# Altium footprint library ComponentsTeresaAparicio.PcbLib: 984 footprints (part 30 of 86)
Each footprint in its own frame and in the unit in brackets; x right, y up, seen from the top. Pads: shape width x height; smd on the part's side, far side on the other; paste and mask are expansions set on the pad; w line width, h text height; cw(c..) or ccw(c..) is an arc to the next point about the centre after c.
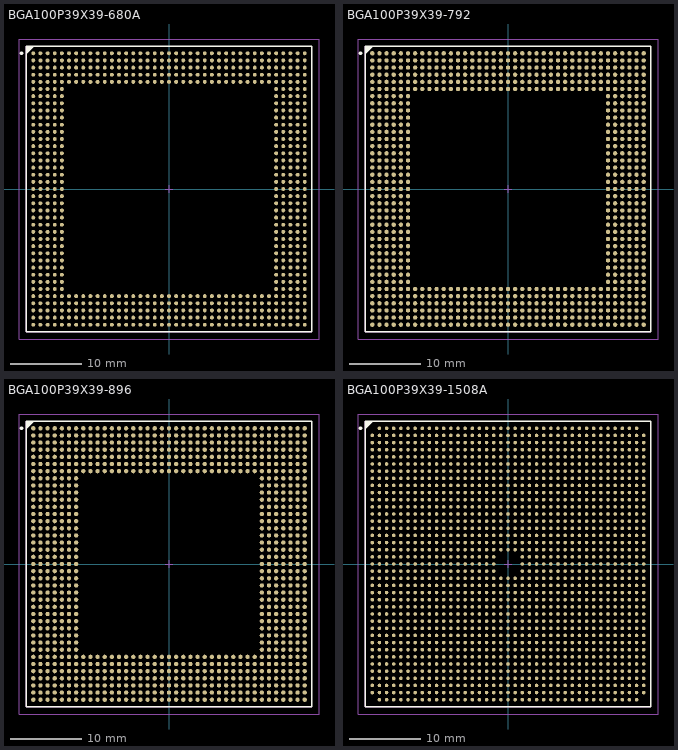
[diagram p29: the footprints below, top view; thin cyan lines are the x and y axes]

## BGA100P39X39-680A [mm] "BGA, 680-Leads, Body 40x40mm, Pitch 1mm"
height 1.7
pads (680):
  round 0.55 smd: A1(-19,19) A2(-18,19) A3(-17,19) A4(-16,19) A5(-15,19) A6(-14,19) A7(-13,19) A8(-12,19) A9(-11,19) A10(-10,19) A11(-9,19) A12(-8,19) A13(-7,19) A14(-6,19) A15(-5,19) A16(-4,19) A17(-3,19) A18(-2,19) A19(-1,19) A20(0,19) A21(1,19) A22(2,19) A23(3,19) A24(4,19) A25(5,19) A26(6,19) A27(7,19) A28(8,19) A29(9,19) A30(10,19) A31(11,19) A32(12,19) A33(13,19) A34(14,19) A35(15,19) A36(16,19) A37(17,19) A38(18,19) A39(19,19) AA1(-19,-1) AA2(-18,-1) AA3(-17,-1) AA4(-16,-1) AA5(-15,-1) AA35(15,-1) AA36(16,-1) AA37(17,-1) AA38(18,-1) AA39(19,-1) AB1(-19,-2) AB2(-18,-2) AB3(-17,-2) AB4(-16,-2) AB5(-15,-2) AB35(15,-2) AB36(16,-2) AB37(17,-2) AB38(18,-2) AB39(19,-2) AC1(-19,-3) AC2(-18,-3) AC3(-17,-3) AC4(-16,-3) AC5(-15,-3) AC35(15,-3) AC36(16,-3) AC37(17,-3) AC38(18,-3) AC39(19,-3) AD1(-19,-4) AD2(-18,-4) AD3(-17,-4) AD4(-16,-4) AD5(-15,-4) AD35(15,-4) AD36(16,-4) AD37(17,-4) AD38(18,-4) AD39(19,-4) AE1(-19,-5) AE2(-18,-5) AE3(-17,-5) AE4(-16,-5) AE5(-15,-5) AE35(15,-5) AE36(16,-5) AE37(17,-5) AE38(18,-5) AE39(19,-5) AF1(-19,-6) AF2(-18,-6) AF3(-17,-6) AF4(-16,-6) AF5(-15,-6) AF35(15,-6) AF36(16,-6) AF37(17,-6) AF38(18,-6) AF39(19,-6) AG1(-19,-7) AG2(-18,-7) AG3(-17,-7) AG4(-16,-7) AG5(-15,-7) AG35(15,-7) AG36(16,-7) AG37(17,-7) AG38(18,-7) AG39(19,-7) AH1(-19,-8) AH2(-18,-8) AH3(-17,-8) AH4(-16,-8) AH5(-15,-8) AH35(15,-8) AH36(16,-8) AH37(17,-8) AH38(18,-8) AH39(19,-8) AJ1(-19,-9) AJ2(-18,-9) AJ3(-17,-9) AJ4(-16,-9) AJ5(-15,-9) AJ35(15,-9) AJ36(16,-9) AJ37(17,-9) AJ38(18,-9) AJ39(19,-9) AK1(-19,-10) AK2(-18,-10) AK3(-17,-10) AK4(-16,-10) AK5(-15,-10) AK35(15,-10) AK36(16,-10) AK37(17,-10) AK38(18,-10) AK39(19,-10) AL1(-19,-11) AL2(-18,-11) AL3(-17,-11) AL4(-16,-11) AL5(-15,-11) AL35(15,-11) AL36(16,-11) AL37(17,-11) AL38(18,-11) AL39(19,-11) AM1(-19,-12) AM2(-18,-12) AM3(-17,-12) AM4(-16,-12) AM5(-15,-12) AM35(15,-12) AM36(16,-12) AM37(17,-12) AM38(18,-12) AM39(19,-12) AN1(-19,-13) AN2(-18,-13) AN3(-17,-13) AN4(-16,-13) AN5(-15,-13) AN35(15,-13) AN36(16,-13) AN37(17,-13) AN38(18,-13) AN39(19,-13) AP1(-19,-14) AP2(-18,-14) AP3(-17,-14) AP4(-16,-14) AP5(-15,-14) AP35(15,-14) AP36(16,-14) AP37(17,-14) AP38(18,-14) AP39(19,-14) AR1(-19,-15) AR2(-18,-15) AR3(-17,-15) AR4(-16,-15) AR5(-15,-15) AR6(-14,-15) AR7(-13,-15) AR8(-12,-15) AR9(-11,-15) AR10(-10,-15) AR11(-9,-15) AR12(-8,-15) AR13(-7,-15) AR14(-6,-15) AR15(-5,-15) AR16(-4,-15) AR17(-3,-15) AR18(-2,-15) AR19(-1,-15) AR20(0,-15) AR21(1,-15) AR22(2,-15) AR23(3,-15) AR24(4,-15) AR25(5,-15) AR26(6,-15) AR27(7,-15) AR28(8,-15) AR29(9,-15) AR30(10,-15) AR31(11,-15) AR32(12,-15) AR33(13,-15) AR34(14,-15) AR35(15,-15) AR36(16,-15) AR37(17,-15) AR38(18,-15) AR39(19,-15) AT1(-19,-16) AT2(-18,-16) AT3(-17,-16) AT4(-16,-16) AT5(-15,-16) AT6(-14,-16) AT7(-13,-16) AT8(-12,-16) AT9(-11,-16) AT10(-10,-16) AT11(-9,-16) AT12(-8,-16) AT13(-7,-16) AT14(-6,-16) AT15(-5,-16) AT16(-4,-16) AT17(-3,-16) AT18(-2,-16) AT19(-1,-16) AT20(0,-16) AT21(1,-16) AT22(2,-16) AT23(3,-16) AT24(4,-16) AT25(5,-16) AT26(6,-16) AT27(7,-16) AT28(8,-16) AT29(9,-16) AT30(10,-16) AT31(11,-16) AT32(12,-16) AT33(13,-16) AT34(14,-16) AT35(15,-16) AT36(16,-16) AT37(17,-16) AT38(18,-16) AT39(19,-16) AU1(-19,-17) AU2(-18,-17) AU3(-17,-17) AU4(-16,-17) AU5(-15,-17) AU6(-14,-17) AU7(-13,-17) AU8(-12,-17) AU9(-11,-17) AU10(-10,-17) AU11(-9,-17) AU12(-8,-17) AU13(-7,-17) AU14(-6,-17) AU15(-5,-17) AU16(-4,-17) AU17(-3,-17) AU18(-2,-17) AU19(-1,-17) AU20(0,-17) AU21(1,-17) AU22(2,-17) AU23(3,-17) AU24(4,-17) AU25(5,-17) AU26(6,-17) AU27(7,-17) AU28(8,-17) AU29(9,-17) AU30(10,-17) AU31(11,-17) AU32(12,-17) AU33(13,-17) AU34(14,-17) AU35(15,-17) AU36(16,-17) AU37(17,-17) AU38(18,-17) AU39(19,-17) AV1(-19,-18) AV2(-18,-18) AV3(-17,-18) AV4(-16,-18) AV5(-15,-18) AV6(-14,-18) AV7(-13,-18) AV8(-12,-18) AV9(-11,-18) AV10(-10,-18) AV11(-9,-18) AV12(-8,-18) AV13(-7,-18) AV14(-6,-18) AV15(-5,-18) AV16(-4,-18) AV17(-3,-18) AV18(-2,-18) AV19(-1,-18) AV20(0,-18) AV21(1,-18) AV22(2,-18) AV23(3,-18) AV24(4,-18) AV25(5,-18) AV26(6,-18) AV27(7,-18) AV28(8,-18) AV29(9,-18) AV30(10,-18) AV31(11,-18) AV32(12,-18) AV33(13,-18) AV34(14,-18) AV35(15,-18) AV36(16,-18) AV37(17,-18) AV38(18,-18) AV39(19,-18) AW1(-19,-19) AW2(-18,-19) AW3(-17,-19) AW4(-16,-19) AW5(-15,-19) AW6(-14,-19) AW7(-13,-19) AW8(-12,-19) AW9(-11,-19) AW10(-10,-19) AW11(-9,-19) AW12(-8,-19) AW13(-7,-19) AW14(-6,-19) AW15(-5,-19) AW16(-4,-19) AW17(-3,-19) AW18(-2,-19) AW19(-1,-19) AW20(0,-19) AW21(1,-19) AW22(2,-19) AW23(3,-19) AW24(4,-19) AW25(5,-19) AW26(6,-19) AW27(7,-19) AW28(8,-19) AW29(9,-19) AW30(10,-19) AW31(11,-19) AW32(12,-19) AW33(13,-19) AW34(14,-19) AW35(15,-19) AW36(16,-19) AW37(17,-19) AW38(18,-19) AW39(19,-19) B1(-19,18) B2(-18,18) B3(-17,18) B4(-16,18) B5(-15,18) B6(-14,18) B7(-13,18) B8(-12,18) B9(-11,18) B10(-10,18) B11(-9,18) B12(-8,18) B13(-7,18) B14(-6,18) B15(-5,18) B16(-4,18) B17(-3,18) B18(-2,18) B19(-1,18) B20(0,18) B21(1,18) B22(2,18) B23(3,18) B24(4,18) B25(5,18) B26(6,18) B27(7,18) B28(8,18) B29(9,18) B30(10,18) B31(11,18) B32(12,18) B33(13,18) B34(14,18) B35(15,18) B36(16,18) B37(17,18) B38(18,18) B39(19,18) C1(-19,17) C2(-18,17) C3(-17,17) C4(-16,17) C5(-15,17) C6(-14,17) C7(-13,17) C8(-12,17) C9(-11,17) C10(-10,17) C11(-9,17) C12(-8,17) C13(-7,17) C14(-6,17) C15(-5,17) C16(-4,17) C17(-3,17) C18(-2,17) C19(-1,17) C20(0,17) C21(1,17) C22(2,17) C23(3,17) C24(4,17) C25(5,17) C26(6,17) C27(7,17) C28(8,17) C29(9,17) C30(10,17) C31(11,17) C32(12,17) C33(13,17) C34(14,17) C35(15,17) C36(16,17) C37(17,17) C38(18,17) C39(19,17) D1(-19,16) D2(-18,16) D3(-17,16) D4(-16,16) D5(-15,16) D6(-14,16) D7(-13,16) D8(-12,16) D9(-11,16) D10(-10,16) D11(-9,16) D12(-8,16) D13(-7,16) D14(-6,16) D15(-5,16) D16(-4,16) D17(-3,16) D18(-2,16) D19(-1,16) D20(0,16) D21(1,16) D22(2,16) D23(3,16) D24(4,16) D25(5,16) D26(6,16) D27(7,16) D28(8,16) D29(9,16) D30(10,16) D31(11,16) D32(12,16) D33(13,16) D34(14,16) D35(15,16) D36(16,16) D37(17,16) D38(18,16) D39(19,16) E1(-19,15) E2(-18,15) E3(-17,15) E4(-16,15) E5(-15,15) E6(-14,15) E7(-13,15) E8(-12,15) E9(-11,15) E10(-10,15) E11(-9,15) E12(-8,15) E13(-7,15) E14(-6,15) E15(-5,15) E16(-4,15) E17(-3,15) E18(-2,15) E19(-1,15) E20(0,15) E21(1,15) E22(2,15) E23(3,15) E24(4,15) E25(5,15) E26(6,15) E27(7,15) E28(8,15) E29(9,15) E30(10,15) E31(11,15) E32(12,15) E33(13,15) E34(14,15) E35(15,15) E36(16,15) E37(17,15) E38(18,15) E39(19,15) F1(-19,14) F2(-18,14) F3(-17,14) F4(-16,14) F5(-15,14) F35(15,14) F36(16,14) F37(17,14) F38(18,14) F39(19,14) G1(-19,13) G2(-18,13) G3(-17,13) G4(-16,13) G5(-15,13) G35(15,13) G36(16,13) G37(17,13) G38(18,13) G39(19,13) H1(-19,12) H2(-18,12) H3(-17,12) H4(-16,12) H5(-15,12) H35(15,12) H36(16,12) H37(17,12) H38(18,12) H39(19,12) J1(-19,11) J2(-18,11) J3(-17,11) J4(-16,11) J5(-15,11) J35(15,11) J36(16,11) J37(17,11) J38(18,11) J39(19,11) K1(-19,10) K2(-18,10) K3(-17,10) K4(-16,10) K5(-15,10) K35(15,10) K36(16,10) K37(17,10) K38(18,10) K39(19,10) L1(-19,9) L2(-18,9) L3(-17,9) L4(-16,9) L5(-15,9) L35(15,9) L36(16,9) L37(17,9) L38(18,9) L39(19,9) M1(-19,8) M2(-18,8) M3(-17,8) M4(-16,8) M5(-15,8) M35(15,8) M36(16,8) M37(17,8) M38(18,8) M39(19,8) N1(-19,7) N2(-18,7) N3(-17,7) N4(-16,7) N5(-15,7) N35(15,7) N36(16,7) N37(17,7) N38(18,7) N39(19,7) P1(-19,6) P2(-18,6) P3(-17,6) P4(-16,6) P5(-15,6) P35(15,6) P36(16,6) P37(17,6) P38(18,6) P39(19,6) R1(-19,5) R2(-18,5) R3(-17,5) R4(-16,5) R5(-15,5) R35(15,5) R36(16,5) R37(17,5) R38(18,5) R39(19,5) T1(-19,4) T2(-18,4) T3(-17,4) T4(-16,4) T5(-15,4) T35(15,4) T36(16,4) T37(17,4) T38(18,4) T39(19,4) U1(-19,3) U2(-18,3) U3(-17,3) U4(-16,3) U5(-15,3) U35(15,3) U36(16,3) U37(17,3) U38(18,3) U39(19,3) V1(-19,2) V2(-18,2) V3(-17,2) V4(-16,2) V5(-15,2) V35(15,2) V36(16,2) V37(17,2) V38(18,2) V39(19,2) W1(-19,1) W2(-18,1) W3(-17,1) W4(-16,1) W5(-15,1) W35(15,1) W36(16,1) W37(17,1) W38(18,1) W39(19,1) Y1(-19,0) Y2(-18,0) Y3(-17,0) Y4(-16,0) Y5(-15,0) Y35(15,0) Y36(16,0) Y37(17,0) Y38(18,0) Y39(19,0)
Top Overlay:
  circle w0.25: c-20.65,19 r0.125
  region: -19,20 -20,19 -20,20
  lines w0.2: -20,19 -19,20 ; -20,-20 20,-20 20,20 -20,20 -20,-20
Mechanical 13:
  lines w0.1: -20,-20 20,-20 20,20 -20,20 -20,-20
Mechanical 15:
  lines w0.1: -0.5,0 0.5,0 ; 0,-0.5 0,0.5 ; -21,-21 21,-21 21,21 -21,21 -21,-21
3D body: height 0, standoff 0, extent -20,-20 20,20

## BGA100P39X39-792 [mm] "792-Ball Ball Grid Array 1 mm Pitch"
height 1.7
pads (792):
  round 0.6 smd: A1(-19,19) A2(-18,19) A3(-17,19) A4(-16,19) A5(-15,19) A6(-14,19) A7(-13,19) A8(-12,19) A9(-11,19) A10(-10,19) A11(-9,19) A12(-8,19) A13(-7,19) A14(-6,19) A15(-5,19) A16(-4,19) A17(-3,19) A18(-2,19) A19(-1,19) A20(0,19) A21(1,19) A22(2,19) A23(3,19) A24(4,19) A25(5,19) A26(6,19) A27(7,19) A28(8,19) A29(9,19) A30(10,19) A31(11,19) A32(12,19) A33(13,19) A34(14,19) A35(15,19) A36(16,19) A37(17,19) A38(18,19) A39(19,19) AA1(-19,-1) AA2(-18,-1) AA3(-17,-1) AA4(-16,-1) AA5(-15,-1) AA6(-14,-1) AA34(14,-1) AA35(15,-1) AA36(16,-1) AA37(17,-1) AA38(18,-1) AA39(19,-1) AB1(-19,-2) AB2(-18,-2) AB3(-17,-2) AB4(-16,-2) AB5(-15,-2) AB6(-14,-2) AB34(14,-2) AB35(15,-2) AB36(16,-2) AB37(17,-2) AB38(18,-2) AB39(19,-2) AC1(-19,-3) AC2(-18,-3) AC3(-17,-3) AC4(-16,-3) AC5(-15,-3) AC6(-14,-3) AC34(14,-3) AC35(15,-3) AC36(16,-3) AC37(17,-3) AC38(18,-3) AC39(19,-3) AD1(-19,-4) AD2(-18,-4) AD3(-17,-4) AD4(-16,-4) AD5(-15,-4) AD6(-14,-4) AD34(14,-4) AD35(15,-4) AD36(16,-4) AD37(17,-4) AD38(18,-4) AD39(19,-4) AE1(-19,-5) AE2(-18,-5) AE3(-17,-5) AE4(-16,-5) AE5(-15,-5) AE6(-14,-5) AE34(14,-5) AE35(15,-5) AE36(16,-5) AE37(17,-5) AE38(18,-5) AE39(19,-5) AF1(-19,-6) AF2(-18,-6) AF3(-17,-6) AF4(-16,-6) AF5(-15,-6) AF6(-14,-6) AF34(14,-6) AF35(15,-6) AF36(16,-6) AF37(17,-6) AF38(18,-6) AF39(19,-6) AG1(-19,-7) AG2(-18,-7) AG3(-17,-7) AG4(-16,-7) AG5(-15,-7) AG6(-14,-7) AG34(14,-7) AG35(15,-7) AG36(16,-7) AG37(17,-7) AG38(18,-7) AG39(19,-7) AH1(-19,-8) AH2(-18,-8) AH3(-17,-8) AH4(-16,-8) AH5(-15,-8) AH6(-14,-8) AH34(14,-8) AH35(15,-8) AH36(16,-8) AH37(17,-8) AH38(18,-8) AH39(19,-8) AJ1(-19,-9) AJ2(-18,-9) AJ3(-17,-9) AJ4(-16,-9) AJ5(-15,-9) AJ6(-14,-9) AJ34(14,-9) AJ35(15,-9) AJ36(16,-9) AJ37(17,-9) AJ38(18,-9) AJ39(19,-9) AK1(-19,-10) AK2(-18,-10) AK3(-17,-10) AK4(-16,-10) AK5(-15,-10) AK6(-14,-10) AK34(14,-10) AK35(15,-10) AK36(16,-10) AK37(17,-10) AK38(18,-10) AK39(19,-10) AL1(-19,-11) AL2(-18,-11) AL3(-17,-11) AL4(-16,-11) AL5(-15,-11) AL6(-14,-11) AL34(14,-11) AL35(15,-11) AL36(16,-11) AL37(17,-11) AL38(18,-11) AL39(19,-11) AM1(-19,-12) AM2(-18,-12) AM3(-17,-12) AM4(-16,-12) AM5(-15,-12) AM6(-14,-12) AM34(14,-12) AM35(15,-12) AM36(16,-12) AM37(17,-12) AM38(18,-12) AM39(19,-12) AN1(-19,-13) AN2(-18,-13) AN3(-17,-13) AN4(-16,-13) AN5(-15,-13) AN6(-14,-13) AN34(14,-13) AN35(15,-13) AN36(16,-13) AN37(17,-13) AN38(18,-13) AN39(19,-13) AP1(-19,-14) AP2(-18,-14) AP3(-17,-14) AP4(-16,-14) AP5(-15,-14) AP6(-14,-14) AP7(-13,-14) AP8(-12,-14) AP9(-11,-14) AP10(-10,-14) AP11(-9,-14) AP12(-8,-14) AP13(-7,-14) AP14(-6,-14) AP15(-5,-14) AP16(-4,-14) AP17(-3,-14) AP18(-2,-14) AP19(-1,-14) AP20(0,-14) AP21(1,-14) AP22(2,-14) AP23(3,-14) AP24(4,-14) AP25(5,-14) AP26(6,-14) AP27(7,-14) AP28(8,-14) AP29(9,-14) AP30(10,-14) AP31(11,-14) AP32(12,-14) AP33(13,-14) AP34(14,-14) AP35(15,-14) AP36(16,-14) AP37(17,-14) AP38(18,-14) AP39(19,-14) AR1(-19,-15) AR2(-18,-15) AR3(-17,-15) AR4(-16,-15) AR5(-15,-15) AR6(-14,-15) AR7(-13,-15) AR8(-12,-15) AR9(-11,-15) AR10(-10,-15) AR11(-9,-15) AR12(-8,-15) AR13(-7,-15) AR14(-6,-15) AR15(-5,-15) AR16(-4,-15) AR17(-3,-15) AR18(-2,-15) AR19(-1,-15) AR20(0,-15) AR21(1,-15) AR22(2,-15) AR23(3,-15) AR24(4,-15) AR25(5,-15) AR26(6,-15) AR27(7,-15) AR28(8,-15) AR29(9,-15) AR30(10,-15) AR31(11,-15) AR32(12,-15) AR33(13,-15) AR34(14,-15) AR35(15,-15) AR36(16,-15) AR37(17,-15) AR38(18,-15) AR39(19,-15) AT1(-19,-16) AT2(-18,-16) AT3(-17,-16) AT4(-16,-16) AT5(-15,-16) AT6(-14,-16) AT7(-13,-16) AT8(-12,-16) AT9(-11,-16) AT10(-10,-16) AT11(-9,-16) AT12(-8,-16) AT13(-7,-16) AT14(-6,-16) AT15(-5,-16) AT16(-4,-16) AT17(-3,-16) AT18(-2,-16) AT19(-1,-16) AT20(0,-16) AT21(1,-16) AT22(2,-16) AT23(3,-16) AT24(4,-16) AT25(5,-16) AT26(6,-16) AT27(7,-16) AT28(8,-16) AT29(9,-16) AT30(10,-16) AT31(11,-16) AT32(12,-16) AT33(13,-16) AT34(14,-16) AT35(15,-16) AT36(16,-16) AT37(17,-16) AT38(18,-16) AT39(19,-16) AU1(-19,-17) AU2(-18,-17) AU3(-17,-17) AU4(-16,-17) AU5(-15,-17) AU6(-14,-17) AU7(-13,-17) AU8(-12,-17) AU9(-11,-17) AU10(-10,-17) AU11(-9,-17) AU12(-8,-17) AU13(-7,-17) AU14(-6,-17) AU15(-5,-17) AU16(-4,-17) AU17(-3,-17) AU18(-2,-17) AU19(-1,-17) AU20(0,-17) AU21(1,-17) AU22(2,-17) AU23(3,-17) AU24(4,-17) AU25(5,-17) AU26(6,-17) AU27(7,-17) AU28(8,-17) AU29(9,-17) AU30(10,-17) AU31(11,-17) AU32(12,-17) AU33(13,-17) AU34(14,-17) AU35(15,-17) AU36(16,-17) AU37(17,-17) AU38(18,-17) AU39(19,-17) AV1(-19,-18) AV2(-18,-18) AV3(-17,-18) AV4(-16,-18) AV5(-15,-18) AV6(-14,-18) AV7(-13,-18) AV8(-12,-18) AV9(-11,-18) AV10(-10,-18) AV11(-9,-18) AV12(-8,-18) AV13(-7,-18) AV14(-6,-18) AV15(-5,-18) AV16(-4,-18) AV17(-3,-18) AV18(-2,-18) AV19(-1,-18) AV20(0,-18) AV21(1,-18) AV22(2,-18) AV23(3,-18) AV24(4,-18) AV25(5,-18) AV26(6,-18) AV27(7,-18) AV28(8,-18) AV29(9,-18) AV30(10,-18) AV31(11,-18) AV32(12,-18) AV33(13,-18) AV34(14,-18) AV35(15,-18) AV36(16,-18) AV37(17,-18) AV38(18,-18) AV39(19,-18) AW1(-19,-19) AW2(-18,-19) AW3(-17,-19) AW4(-16,-19) AW5(-15,-19) AW6(-14,-19) AW7(-13,-19) AW8(-12,-19) AW9(-11,-19) AW10(-10,-19) AW11(-9,-19) AW12(-8,-19) AW13(-7,-19) AW14(-6,-19) AW15(-5,-19) AW16(-4,-19) AW17(-3,-19) AW18(-2,-19) AW19(-1,-19) AW20(0,-19) AW21(1,-19) AW22(2,-19) AW23(3,-19) AW24(4,-19) AW25(5,-19) AW26(6,-19) AW27(7,-19) AW28(8,-19) AW29(9,-19) AW30(10,-19) AW31(11,-19) AW32(12,-19) AW33(13,-19) AW34(14,-19) AW35(15,-19) AW36(16,-19) AW37(17,-19) AW38(18,-19) AW39(19,-19) B1(-19,18) B2(-18,18) B3(-17,18) B4(-16,18) B5(-15,18) B6(-14,18) B7(-13,18) B8(-12,18) B9(-11,18) B10(-10,18) B11(-9,18) B12(-8,18) B13(-7,18) B14(-6,18) B15(-5,18) B16(-4,18) B17(-3,18) B18(-2,18) B19(-1,18) B20(0,18) B21(1,18) B22(2,18) B23(3,18) B24(4,18) B25(5,18) B26(6,18) B27(7,18) B28(8,18) B29(9,18) B30(10,18) B31(11,18) B32(12,18) B33(13,18) B34(14,18) B35(15,18) B36(16,18) B37(17,18) B38(18,18) B39(19,18) C1(-19,17) C2(-18,17) C3(-17,17) C4(-16,17) C5(-15,17) C6(-14,17) C7(-13,17) C8(-12,17) C9(-11,17) C10(-10,17) C11(-9,17) C12(-8,17) C13(-7,17) C14(-6,17) C15(-5,17) C16(-4,17) C17(-3,17) C18(-2,17) C19(-1,17) C20(0,17) C21(1,17) C22(2,17) C23(3,17) C24(4,17) C25(5,17) C26(6,17) C27(7,17) C28(8,17) C29(9,17) C30(10,17) C31(11,17) C32(12,17) C33(13,17) C34(14,17) C35(15,17) C36(16,17) C37(17,17) C38(18,17) C39(19,17) D1(-19,16) D2(-18,16) D3(-17,16) D4(-16,16) D5(-15,16) D6(-14,16) D7(-13,16) D8(-12,16) D9(-11,16) D10(-10,16) D11(-9,16) D12(-8,16) D13(-7,16) D14(-6,16) D15(-5,16) D16(-4,16) D17(-3,16) D18(-2,16) D19(-1,16) D20(0,16) D21(1,16) D22(2,16) D23(3,16) D24(4,16) D25(5,16) D26(6,16) D27(7,16) D28(8,16) D29(9,16) D30(10,16) D31(11,16) D32(12,16) D33(13,16) D34(14,16) D35(15,16) D36(16,16) D37(17,16) D38(18,16) D39(19,16) E1(-19,15) E2(-18,15) E3(-17,15) E4(-16,15) E5(-15,15) E6(-14,15) E7(-13,15) E8(-12,15) E9(-11,15) E10(-10,15) E11(-9,15) E12(-8,15) E13(-7,15) E14(-6,15) E15(-5,15) E16(-4,15) E17(-3,15) E18(-2,15) E19(-1,15) E20(0,15) E21(1,15) E22(2,15) E23(3,15) E24(4,15) E25(5,15) E26(6,15) E27(7,15) E28(8,15) E29(9,15) E30(10,15) E31(11,15) E32(12,15) E33(13,15) E34(14,15) E35(15,15) E36(16,15) E37(17,15) E38(18,15) E39(19,15) F1(-19,14) F2(-18,14) F3(-17,14) F4(-16,14) F5(-15,14) F6(-14,14) F7(-13,14) F8(-12,14) F9(-11,14) F10(-10,14) F11(-9,14) F12(-8,14) F13(-7,14) F14(-6,14) F15(-5,14) F16(-4,14) F17(-3,14) F18(-2,14) F19(-1,14) F20(0,14) F21(1,14) F22(2,14) F23(3,14) F24(4,14) F25(5,14) F26(6,14) F27(7,14) F28(8,14) F29(9,14) F30(10,14) F31(11,14) F32(12,14) F33(13,14) F34(14,14) F35(15,14) F36(16,14) F37(17,14) F38(18,14) F39(19,14) G1(-19,13) G2(-18,13) G3(-17,13) G4(-16,13) G5(-15,13) G6(-14,13) G34(14,13) G35(15,13) G36(16,13) G37(17,13) G38(18,13) G39(19,13) H1(-19,12) H2(-18,12) H3(-17,12) H4(-16,12) H5(-15,12) H6(-14,12) H34(14,12) H35(15,12) H36(16,12) H37(17,12) H38(18,12) H39(19,12) J1(-19,11) J2(-18,11) J3(-17,11) J4(-16,11) J5(-15,11) J6(-14,11) J34(14,11) J35(15,11) J36(16,11) J37(17,11) J38(18,11) J39(19,11) K1(-19,10) K2(-18,10) K3(-17,10) K4(-16,10) K5(-15,10) K6(-14,10) K34(14,10) K35(15,10) K36(16,10) K37(17,10) K38(18,10) K39(19,10) L1(-19,9) L2(-18,9) L3(-17,9) L4(-16,9) L5(-15,9) L6(-14,9) L34(14,9) L35(15,9) L36(16,9) L37(17,9) L38(18,9) L39(19,9) M1(-19,8) M2(-18,8) M3(-17,8) M4(-16,8) M5(-15,8) M6(-14,8) M34(14,8) M35(15,8) M36(16,8) M37(17,8) M38(18,8) M39(19,8) N1(-19,7) N2(-18,7) N3(-17,7) N4(-16,7) N5(-15,7) N6(-14,7) N34(14,7) N35(15,7) N36(16,7) N37(17,7) N38(18,7) N39(19,7) P1(-19,6) P2(-18,6) P3(-17,6) P4(-16,6) P5(-15,6) P6(-14,6) P34(14,6) P35(15,6) P36(16,6) P37(17,6) P38(18,6) P39(19,6) R1(-19,5) R2(-18,5) R3(-17,5) R4(-16,5) R5(-15,5) R6(-14,5) R34(14,5) R35(15,5) R36(16,5) R37(17,5) R38(18,5) R39(19,5) T1(-19,4) T2(-18,4) T3(-17,4) T4(-16,4) T5(-15,4) T6(-14,4) T34(14,4) T35(15,4) T36(16,4) T37(17,4) T38(18,4) T39(19,4) U1(-19,3) U2(-18,3) U3(-17,3) U4(-16,3) U5(-15,3) U6(-14,3) U34(14,3) U35(15,3) U36(16,3) U37(17,3) U38(18,3) U39(19,3) V1(-19,2) V2(-18,2) V3(-17,2) V4(-16,2) V5(-15,2) V6(-14,2) V34(14,2) V35(15,2) V36(16,2) V37(17,2) V38(18,2) V39(19,2) W1(-19,1) W2(-18,1) W3(-17,1) W4(-16,1) W5(-15,1) W6(-14,1) W34(14,1) W35(15,1) W36(16,1) W37(17,1) W38(18,1) W39(19,1) Y1(-19,0) Y2(-18,0) Y3(-17,0) Y4(-16,0) Y5(-15,0) Y6(-14,0) Y34(14,0) Y35(15,0) Y36(16,0) Y37(17,0) Y38(18,0) Y39(19,0)
Top Overlay:
  circle w0.25: c-20.65,19 r0.125
  region: -19,20 -20,19 -20,20
  lines w0.2: -20,19 -19,20 ; -20,-20 20,-20 20,20 -20,20 -20,-20
Mechanical 13:
  lines w0.1: -20,-20 20,-20 20,20 -20,20 -20,-20
Mechanical 15:
  lines w0.1: -0.5,0 0.5,0 ; 0,-0.5 0,0.5 ; -21,-21 21,-21 21,21 -21,21 -21,-21
3D body: height 0, standoff 0, extent -20,-20 20,20

## BGA100P39X39-896 [mm] "896-Ball Ball Grid Array 1 mm Pitch"
height 1.7
pads (896):
  round 0.6 smd: A1(-19,19) A2(-18,19) A3(-17,19) A4(-16,19) A5(-15,19) A6(-14,19) A7(-13,19) A8(-12,19) A9(-11,19) A10(-10,19) A11(-9,19) A12(-8,19) A13(-7,19) A14(-6,19) A15(-5,19) A16(-4,19) A17(-3,19) A18(-2,19) A19(-1,19) A20(0,19) A21(1,19) A22(2,19) A23(3,19) A24(4,19) A25(5,19) A26(6,19) A27(7,19) A28(8,19) A29(9,19) A30(10,19) A31(11,19) A32(12,19) A33(13,19) A34(14,19) A35(15,19) A36(16,19) A37(17,19) A38(18,19) A39(19,19) AA1(-19,-1) AA2(-18,-1) AA3(-17,-1) AA4(-16,-1) AA5(-15,-1) AA6(-14,-1) AA7(-13,-1) AA33(13,-1) AA34(14,-1) AA35(15,-1) AA36(16,-1) AA37(17,-1) AA38(18,-1) AA39(19,-1) AB1(-19,-2) AB2(-18,-2) AB3(-17,-2) AB4(-16,-2) AB5(-15,-2) AB6(-14,-2) AB7(-13,-2) AB33(13,-2) AB34(14,-2) AB35(15,-2) AB36(16,-2) AB37(17,-2) AB38(18,-2) AB39(19,-2) AC1(-19,-3) AC2(-18,-3) AC3(-17,-3) AC4(-16,-3) AC5(-15,-3) AC6(-14,-3) AC7(-13,-3) AC33(13,-3) AC34(14,-3) AC35(15,-3) AC36(16,-3) AC37(17,-3) AC38(18,-3) AC39(19,-3) AD1(-19,-4) AD2(-18,-4) AD3(-17,-4) AD4(-16,-4) AD5(-15,-4) AD6(-14,-4) AD7(-13,-4) AD33(13,-4) AD34(14,-4) AD35(15,-4) AD36(16,-4) AD37(17,-4) AD38(18,-4) AD39(19,-4) AE1(-19,-5) AE2(-18,-5) AE3(-17,-5) AE4(-16,-5) AE5(-15,-5) AE6(-14,-5) AE7(-13,-5) AE33(13,-5) AE34(14,-5) AE35(15,-5) AE36(16,-5) AE37(17,-5) AE38(18,-5) AE39(19,-5) AF1(-19,-6) AF2(-18,-6) AF3(-17,-6) AF4(-16,-6) AF5(-15,-6) AF6(-14,-6) AF7(-13,-6) AF33(13,-6) AF34(14,-6) AF35(15,-6) AF36(16,-6) AF37(17,-6) AF38(18,-6) AF39(19,-6) AG1(-19,-7) AG2(-18,-7) AG3(-17,-7) AG4(-16,-7) AG5(-15,-7) AG6(-14,-7) AG7(-13,-7) AG33(13,-7) AG34(14,-7) AG35(15,-7) AG36(16,-7) AG37(17,-7) AG38(18,-7) AG39(19,-7) AH1(-19,-8) AH2(-18,-8) AH3(-17,-8) AH4(-16,-8) AH5(-15,-8) AH6(-14,-8) AH7(-13,-8) AH33(13,-8) AH34(14,-8) AH35(15,-8) AH36(16,-8) AH37(17,-8) AH38(18,-8) AH39(19,-8) AJ1(-19,-9) AJ2(-18,-9) AJ3(-17,-9) AJ4(-16,-9) AJ5(-15,-9) AJ6(-14,-9) AJ7(-13,-9) AJ33(13,-9) AJ34(14,-9) AJ35(15,-9) AJ36(16,-9) AJ37(17,-9) AJ38(18,-9) AJ39(19,-9) AK1(-19,-10) AK2(-18,-10) AK3(-17,-10) AK4(-16,-10) AK5(-15,-10) AK6(-14,-10) AK7(-13,-10) AK33(13,-10) AK34(14,-10) AK35(15,-10) AK36(16,-10) AK37(17,-10) AK38(18,-10) AK39(19,-10) AL1(-19,-11) AL2(-18,-11) AL3(-17,-11) AL4(-16,-11) AL5(-15,-11) AL6(-14,-11) AL7(-13,-11) AL33(13,-11) AL34(14,-11) AL35(15,-11) AL36(16,-11) AL37(17,-11) AL38(18,-11) AL39(19,-11) AM1(-19,-12) AM2(-18,-12) AM3(-17,-12) AM4(-16,-12) AM5(-15,-12) AM6(-14,-12) AM7(-13,-12) AM33(13,-12) AM34(14,-12) AM35(15,-12) AM36(16,-12) AM37(17,-12) AM38(18,-12) AM39(19,-12) AN1(-19,-13) AN2(-18,-13) AN3(-17,-13) AN4(-16,-13) AN5(-15,-13) AN6(-14,-13) AN7(-13,-13) AN8(-12,-13) AN9(-11,-13) AN10(-10,-13) AN11(-9,-13) AN12(-8,-13) AN13(-7,-13) AN14(-6,-13) AN15(-5,-13) AN16(-4,-13) AN17(-3,-13) AN18(-2,-13) AN19(-1,-13) AN20(0,-13) AN21(1,-13) AN22(2,-13) AN23(3,-13) AN24(4,-13) AN25(5,-13) AN26(6,-13) AN27(7,-13) AN28(8,-13) AN29(9,-13) AN30(10,-13) AN31(11,-13) AN32(12,-13) AN33(13,-13) AN34(14,-13) AN35(15,-13) AN36(16,-13) AN37(17,-13) AN38(18,-13) AN39(19,-13) AP1(-19,-14) AP2(-18,-14) AP3(-17,-14) AP4(-16,-14) AP5(-15,-14) AP6(-14,-14) AP7(-13,-14) AP8(-12,-14) AP9(-11,-14) AP10(-10,-14) AP11(-9,-14) AP12(-8,-14) AP13(-7,-14) AP14(-6,-14) AP15(-5,-14) AP16(-4,-14) AP17(-3,-14) AP18(-2,-14) AP19(-1,-14) AP20(0,-14) AP21(1,-14) AP22(2,-14) AP23(3,-14) AP24(4,-14) AP25(5,-14) AP26(6,-14) AP27(7,-14) AP28(8,-14) AP29(9,-14) AP30(10,-14) AP31(11,-14) AP32(12,-14) AP33(13,-14) AP34(14,-14) AP35(15,-14) AP36(16,-14) AP37(17,-14) AP38(18,-14) AP39(19,-14) AR1(-19,-15) AR2(-18,-15) AR3(-17,-15) AR4(-16,-15) AR5(-15,-15) AR6(-14,-15) AR7(-13,-15) AR8(-12,-15) AR9(-11,-15) AR10(-10,-15) AR11(-9,-15) AR12(-8,-15) AR13(-7,-15) AR14(-6,-15) AR15(-5,-15) AR16(-4,-15) AR17(-3,-15) AR18(-2,-15) AR19(-1,-15) AR20(0,-15) AR21(1,-15) AR22(2,-15) AR23(3,-15) AR24(4,-15) AR25(5,-15) AR26(6,-15) AR27(7,-15) AR28(8,-15) AR29(9,-15) AR30(10,-15) AR31(11,-15) AR32(12,-15) AR33(13,-15) AR34(14,-15) AR35(15,-15) AR36(16,-15) AR37(17,-15) AR38(18,-15) AR39(19,-15) AT1(-19,-16) AT2(-18,-16) AT3(-17,-16) AT4(-16,-16) AT5(-15,-16) AT6(-14,-16) AT7(-13,-16) AT8(-12,-16) AT9(-11,-16) AT10(-10,-16) AT11(-9,-16) AT12(-8,-16) AT13(-7,-16) AT14(-6,-16) AT15(-5,-16) AT16(-4,-16) AT17(-3,-16) AT18(-2,-16) AT19(-1,-16) AT20(0,-16) AT21(1,-16) AT22(2,-16) AT23(3,-16) AT24(4,-16) AT25(5,-16) AT26(6,-16) AT27(7,-16) AT28(8,-16) AT29(9,-16) AT30(10,-16) AT31(11,-16) AT32(12,-16) AT33(13,-16) AT34(14,-16) AT35(15,-16) AT36(16,-16) AT37(17,-16) AT38(18,-16) AT39(19,-16) AU1(-19,-17) AU2(-18,-17) AU3(-17,-17) AU4(-16,-17) AU5(-15,-17) AU6(-14,-17) AU7(-13,-17) AU8(-12,-17) AU9(-11,-17) AU10(-10,-17) AU11(-9,-17) AU12(-8,-17) AU13(-7,-17) AU14(-6,-17) AU15(-5,-17) AU16(-4,-17) AU17(-3,-17) AU18(-2,-17) AU19(-1,-17) AU20(0,-17) AU21(1,-17) AU22(2,-17) AU23(3,-17) AU24(4,-17) AU25(5,-17) AU26(6,-17) AU27(7,-17) AU28(8,-17) AU29(9,-17) AU30(10,-17) AU31(11,-17) AU32(12,-17) AU33(13,-17) AU34(14,-17) AU35(15,-17) AU36(16,-17) AU37(17,-17) AU38(18,-17) AU39(19,-17) AV1(-19,-18) AV2(-18,-18) AV3(-17,-18) AV4(-16,-18) AV5(-15,-18) AV6(-14,-18) AV7(-13,-18) AV8(-12,-18) AV9(-11,-18) AV10(-10,-18) AV11(-9,-18) AV12(-8,-18) AV13(-7,-18) AV14(-6,-18) AV15(-5,-18) AV16(-4,-18) AV17(-3,-18) AV18(-2,-18) AV19(-1,-18) AV20(0,-18) AV21(1,-18) AV22(2,-18) AV23(3,-18) AV24(4,-18) AV25(5,-18) AV26(6,-18) AV27(7,-18) AV28(8,-18) AV29(9,-18) AV30(10,-18) AV31(11,-18) AV32(12,-18) AV33(13,-18) AV34(14,-18) AV35(15,-18) AV36(16,-18) AV37(17,-18) AV38(18,-18) AV39(19,-18) AW1(-19,-19) AW2(-18,-19) AW3(-17,-19) AW4(-16,-19) AW5(-15,-19) AW6(-14,-19) AW7(-13,-19) AW8(-12,-19) AW9(-11,-19) AW10(-10,-19) AW11(-9,-19) AW12(-8,-19) AW13(-7,-19) AW14(-6,-19) AW15(-5,-19) AW16(-4,-19) AW17(-3,-19) AW18(-2,-19) AW19(-1,-19) AW20(0,-19) AW21(1,-19) AW22(2,-19) AW23(3,-19) AW24(4,-19) AW25(5,-19) AW26(6,-19) AW27(7,-19) AW28(8,-19) AW29(9,-19) AW30(10,-19) AW31(11,-19) AW32(12,-19) AW33(13,-19) AW34(14,-19) AW35(15,-19) AW36(16,-19) AW37(17,-19) AW38(18,-19) AW39(19,-19) B1(-19,18) B2(-18,18) B3(-17,18) B4(-16,18) B5(-15,18) B6(-14,18) B7(-13,18) B8(-12,18) B9(-11,18) B10(-10,18) B11(-9,18) B12(-8,18) B13(-7,18) B14(-6,18) B15(-5,18) B16(-4,18) B17(-3,18) B18(-2,18) B19(-1,18) B20(0,18) B21(1,18) B22(2,18) B23(3,18) B24(4,18) B25(5,18) B26(6,18) B27(7,18) B28(8,18) B29(9,18) B30(10,18) B31(11,18) B32(12,18) B33(13,18) B34(14,18) B35(15,18) B36(16,18) B37(17,18) B38(18,18) B39(19,18) C1(-19,17) C2(-18,17) C3(-17,17) C4(-16,17) C5(-15,17) C6(-14,17) C7(-13,17) C8(-12,17) C9(-11,17) C10(-10,17) C11(-9,17) C12(-8,17) C13(-7,17) C14(-6,17) C15(-5,17) C16(-4,17) C17(-3,17) C18(-2,17) C19(-1,17) C20(0,17) C21(1,17) C22(2,17) C23(3,17) C24(4,17) C25(5,17) C26(6,17) C27(7,17) C28(8,17) C29(9,17) C30(10,17) C31(11,17) C32(12,17) C33(13,17) C34(14,17) C35(15,17) C36(16,17) C37(17,17) C38(18,17) C39(19,17) D1(-19,16) D2(-18,16) D3(-17,16) D4(-16,16) D5(-15,16) D6(-14,16) D7(-13,16) D8(-12,16) D9(-11,16) D10(-10,16) D11(-9,16) D12(-8,16) D13(-7,16) D14(-6,16) D15(-5,16) D16(-4,16) D17(-3,16) D18(-2,16) D19(-1,16) D20(0,16) D21(1,16) D22(2,16) D23(3,16) D24(4,16) D25(5,16) D26(6,16) D27(7,16) D28(8,16) D29(9,16) D30(10,16) D31(11,16) D32(12,16) D33(13,16) D34(14,16) D35(15,16) D36(16,16) D37(17,16) D38(18,16) D39(19,16) E1(-19,15) E2(-18,15) E3(-17,15) E4(-16,15) E5(-15,15) E6(-14,15) E7(-13,15) E8(-12,15) E9(-11,15) E10(-10,15) E11(-9,15) E12(-8,15) E13(-7,15) E14(-6,15) E15(-5,15) E16(-4,15) E17(-3,15) E18(-2,15) E19(-1,15) E20(0,15) E21(1,15) E22(2,15) E23(3,15) E24(4,15) E25(5,15) E26(6,15) E27(7,15) E28(8,15) E29(9,15) E30(10,15) E31(11,15) E32(12,15) E33(13,15) E34(14,15) E35(15,15) E36(16,15) E37(17,15) E38(18,15) E39(19,15) F1(-19,14) F2(-18,14) F3(-17,14) F4(-16,14) F5(-15,14) F6(-14,14) F7(-13,14) F8(-12,14) F9(-11,14) F10(-10,14) F11(-9,14) F12(-8,14) F13(-7,14) F14(-6,14) F15(-5,14) F16(-4,14) F17(-3,14) F18(-2,14) F19(-1,14) F20(0,14) F21(1,14) F22(2,14) F23(3,14) F24(4,14) F25(5,14) F26(6,14) F27(7,14) F28(8,14) F29(9,14) F30(10,14) F31(11,14) F32(12,14) F33(13,14) F34(14,14) F35(15,14) F36(16,14) F37(17,14) F38(18,14) F39(19,14) G1(-19,13) G2(-18,13) G3(-17,13) G4(-16,13) G5(-15,13) G6(-14,13) G7(-13,13) G8(-12,13) G9(-11,13) G10(-10,13) G11(-9,13) G12(-8,13) G13(-7,13) G14(-6,13) G15(-5,13) G16(-4,13) G17(-3,13) G18(-2,13) G19(-1,13) G20(0,13) G21(1,13) G22(2,13) G23(3,13) G24(4,13) G25(5,13) G26(6,13) G27(7,13) G28(8,13) G29(9,13) G30(10,13) G31(11,13) G32(12,13) G33(13,13) G34(14,13) G35(15,13) G36(16,13) G37(17,13) G38(18,13) G39(19,13) H1(-19,12) H2(-18,12) H3(-17,12) H4(-16,12) H5(-15,12) H6(-14,12) H7(-13,12) H33(13,12) H34(14,12) H35(15,12) H36(16,12) H37(17,12) H38(18,12) H39(19,12) J1(-19,11) J2(-18,11) J3(-17,11) J4(-16,11) J5(-15,11) J6(-14,11) J7(-13,11) J33(13,11) J34(14,11) J35(15,11) J36(16,11) J37(17,11) J38(18,11) J39(19,11) K1(-19,10) K2(-18,10) K3(-17,10) K4(-16,10) K5(-15,10) K6(-14,10) K7(-13,10) K33(13,10) K34(14,10) K35(15,10) K36(16,10) K37(17,10) K38(18,10) K39(19,10) L1(-19,9) L2(-18,9) L3(-17,9) L4(-16,9) L5(-15,9) L6(-14,9) L7(-13,9) L33(13,9) L34(14,9) L35(15,9) L36(16,9) L37(17,9) L38(18,9) L39(19,9) M1(-19,8) M2(-18,8) M3(-17,8) M4(-16,8) M5(-15,8) M6(-14,8) M7(-13,8) M33(13,8) M34(14,8) M35(15,8) M36(16,8) M37(17,8) M38(18,8) M39(19,8) N1(-19,7) N2(-18,7) N3(-17,7) N4(-16,7) N5(-15,7) N6(-14,7) N7(-13,7) N33(13,7) N34(14,7) N35(15,7) N36(16,7) N37(17,7) N38(18,7) N39(19,7) P1(-19,6) P2(-18,6) P3(-17,6) P4(-16,6) P5(-15,6) P6(-14,6) P7(-13,6) P33(13,6) P34(14,6) P35(15,6) P36(16,6) P37(17,6) P38(18,6) P39(19,6) R1(-19,5) R2(-18,5) R3(-17,5) R4(-16,5) R5(-15,5) R6(-14,5) R7(-13,5) R33(13,5) R34(14,5) R35(15,5) R36(16,5) R37(17,5) R38(18,5) R39(19,5) T1(-19,4) T2(-18,4) T3(-17,4) T4(-16,4) T5(-15,4) T6(-14,4) T7(-13,4) T33(13,4) T34(14,4) T35(15,4) T36(16,4) T37(17,4) T38(18,4) T39(19,4) U1(-19,3) U2(-18,3) U3(-17,3) U4(-16,3) U5(-15,3) U6(-14,3) U7(-13,3) U33(13,3) U34(14,3) U35(15,3) U36(16,3) U37(17,3) U38(18,3) U39(19,3) V1(-19,2) V2(-18,2) V3(-17,2) V4(-16,2) V5(-15,2) V6(-14,2) V7(-13,2) V33(13,2) V34(14,2) V35(15,2) V36(16,2) V37(17,2) V38(18,2) V39(19,2) W1(-19,1) W2(-18,1) W3(-17,1) W4(-16,1) W5(-15,1) W6(-14,1) W7(-13,1) W33(13,1) W34(14,1) W35(15,1) W36(16,1) W37(17,1) W38(18,1) W39(19,1) Y1(-19,0) Y2(-18,0) Y3(-17,0) Y4(-16,0) Y5(-15,0) Y6(-14,0) Y7(-13,0) Y33(13,0) Y34(14,0) Y35(15,0) Y36(16,0) Y37(17,0) Y38(18,0) Y39(19,0)
Top Overlay:
  circle w0.25: c-20.65,19 r0.125
  region: -19,20 -20,19 -20,20
  lines w0.2: -20,19 -19,20 ; -20,-20 20,-20 20,20 -20,20 -20,-20
Mechanical 13:
  lines w0.1: -20,-20 20,-20 20,20 -20,20 -20,-20
Mechanical 15:
  lines w0.1: -0.5,0 0.5,0 ; 0,-0.5 0,0.5 ; -21,-21 21,-21 21,21 -21,21 -21,-21
3D body: height 0, standoff 0, extent -20,-20 20,20

## BGA100P39X39-1508A [mm] "BGA, 1508-Leads, Body 40x40mm, Pitch 1mm"
height 3.5
pads (1508):
  round 0.5 smd: A2(-18,19) A3(-17,19) A4(-16,19) A5(-15,19) A6(-14,19) A7(-13,19) A8(-12,19) A9(-11,19) A10(-10,19) A11(-9,19) A12(-8,19) A13(-7,19) A14(-6,19) A15(-5,19) A16(-4,19) A17(-3,19) A18(-2,19) A19(-1,19) A20(0,19) A21(1,19) A22(2,19) A23(3,19) A24(4,19) A25(5,19) A26(6,19) A27(7,19) A28(8,19) A29(9,19) A30(10,19) A31(11,19) A32(12,19) A33(13,19) A34(14,19) A35(15,19) A36(16,19) A37(17,19) A38(18,19) AA1(-19,-1) AA2(-18,-1) AA3(-17,-1) AA4(-16,-1) AA5(-15,-1) AA6(-14,-1) AA7(-13,-1) AA8(-12,-1) AA9(-11,-1) AA10(-10,-1) AA11(-9,-1) AA12(-8,-1) AA13(-7,-1) AA14(-6,-1) AA15(-5,-1) AA16(-4,-1) AA17(-3,-1) AA18(-2,-1) AA22(2,-1) AA23(3,-1) AA24(4,-1) AA25(5,-1) AA26(6,-1) AA27(7,-1) AA28(8,-1) AA29(9,-1) AA30(10,-1) AA31(11,-1) AA32(12,-1) AA33(13,-1) AA34(14,-1) AA35(15,-1) AA36(16,-1) AA37(17,-1) AA38(18,-1) AA39(19,-1) AB1(-19,-2) AB2(-18,-2) AB3(-17,-2) AB4(-16,-2) AB5(-15,-2) AB6(-14,-2) AB7(-13,-2) AB8(-12,-2) AB9(-11,-2) AB10(-10,-2) AB11(-9,-2) AB12(-8,-2) AB13(-7,-2) AB14(-6,-2) AB15(-5,-2) AB16(-4,-2) AB17(-3,-2) AB18(-2,-2) AB19(-1,-2) AB20(0,-2) AB21(1,-2) AB22(2,-2) AB23(3,-2) AB24(4,-2) AB25(5,-2) AB26(6,-2) AB27(7,-2) AB28(8,-2) AB29(9,-2) AB30(10,-2) AB31(11,-2) AB32(12,-2) AB33(13,-2) AB34(14,-2) AB35(15,-2) AB36(16,-2) AB37(17,-2) AB38(18,-2) AB39(19,-2) AC1(-19,-3) AC2(-18,-3) AC3(-17,-3) AC4(-16,-3) AC5(-15,-3) AC6(-14,-3) AC7(-13,-3) AC8(-12,-3) AC9(-11,-3) AC10(-10,-3) AC11(-9,-3) AC12(-8,-3) AC13(-7,-3) AC14(-6,-3) AC15(-5,-3) AC16(-4,-3) AC17(-3,-3) AC18(-2,-3) AC19(-1,-3) AC20(0,-3) AC21(1,-3) AC22(2,-3) AC23(3,-3) AC24(4,-3) AC25(5,-3) AC26(6,-3) AC27(7,-3) AC28(8,-3) AC29(9,-3) AC30(10,-3) AC31(11,-3) AC32(12,-3) AC33(13,-3) AC34(14,-3) AC35(15,-3) AC36(16,-3) AC37(17,-3) AC38(18,-3) AC39(19,-3) AD1(-19,-4) AD2(-18,-4) AD3(-17,-4) AD4(-16,-4) AD5(-15,-4) AD6(-14,-4) AD7(-13,-4) AD8(-12,-4) AD9(-11,-4) AD10(-10,-4) AD11(-9,-4) AD12(-8,-4) AD13(-7,-4) AD14(-6,-4) AD15(-5,-4) AD16(-4,-4) AD17(-3,-4) AD18(-2,-4) AD19(-1,-4) AD20(0,-4) AD21(1,-4) AD22(2,-4) AD23(3,-4) AD24(4,-4) AD25(5,-4) AD26(6,-4) AD27(7,-4) AD28(8,-4) AD29(9,-4) AD30(10,-4) AD31(11,-4) AD32(12,-4) AD33(13,-4) AD34(14,-4) AD35(15,-4) AD36(16,-4) AD37(17,-4) AD38(18,-4) AD39(19,-4) AE1(-19,-5) AE2(-18,-5) AE3(-17,-5) AE4(-16,-5) AE5(-15,-5) AE6(-14,-5) AE7(-13,-5) AE8(-12,-5) AE9(-11,-5) AE10(-10,-5) AE11(-9,-5) AE12(-8,-5) AE13(-7,-5) AE14(-6,-5) AE15(-5,-5) AE16(-4,-5) AE17(-3,-5) AE18(-2,-5) AE19(-1,-5) AE20(0,-5) AE21(1,-5) AE22(2,-5) AE23(3,-5) AE24(4,-5) AE25(5,-5) AE26(6,-5) AE27(7,-5) AE28(8,-5) AE29(9,-5) AE30(10,-5) AE31(11,-5) AE32(12,-5) AE33(13,-5) AE34(14,-5) AE35(15,-5) AE36(16,-5) AE37(17,-5) AE38(18,-5) AE39(19,-5) AF1(-19,-6) AF2(-18,-6) AF3(-17,-6) AF4(-16,-6) AF5(-15,-6) AF6(-14,-6) AF7(-13,-6) AF8(-12,-6) AF9(-11,-6) AF10(-10,-6) AF11(-9,-6) AF12(-8,-6) AF13(-7,-6) AF14(-6,-6) AF15(-5,-6) AF16(-4,-6) AF17(-3,-6) AF18(-2,-6) AF19(-1,-6) AF20(0,-6) AF21(1,-6) AF22(2,-6) AF23(3,-6) AF24(4,-6) AF25(5,-6) AF26(6,-6) AF27(7,-6) AF28(8,-6) AF29(9,-6) AF30(10,-6) AF31(11,-6) AF32(12,-6) AF33(13,-6) AF34(14,-6) AF35(15,-6) AF36(16,-6) AF37(17,-6) AF38(18,-6) AF39(19,-6) AG1(-19,-7) AG2(-18,-7) AG3(-17,-7) AG4(-16,-7) AG5(-15,-7) AG6(-14,-7) AG7(-13,-7) AG8(-12,-7) AG9(-11,-7) AG10(-10,-7) AG11(-9,-7) AG12(-8,-7) AG13(-7,-7) AG14(-6,-7) AG15(-5,-7) AG16(-4,-7) AG17(-3,-7) AG18(-2,-7) AG19(-1,-7) AG20(0,-7) AG21(1,-7) AG22(2,-7) AG23(3,-7) AG24(4,-7) AG25(5,-7) AG26(6,-7) AG27(7,-7) AG28(8,-7) AG29(9,-7) AG30(10,-7) AG31(11,-7) AG32(12,-7) AG33(13,-7) AG34(14,-7) AG35(15,-7) AG36(16,-7) AG37(17,-7) AG38(18,-7) AG39(19,-7) AH1(-19,-8) AH2(-18,-8) AH3(-17,-8) AH4(-16,-8) AH5(-15,-8) AH6(-14,-8) AH7(-13,-8) AH8(-12,-8) AH9(-11,-8) AH10(-10,-8) AH11(-9,-8) AH12(-8,-8) AH13(-7,-8) AH14(-6,-8) AH15(-5,-8) AH16(-4,-8) AH17(-3,-8) AH18(-2,-8) AH19(-1,-8) AH20(0,-8) AH21(1,-8) AH22(2,-8) AH23(3,-8) AH24(4,-8) AH25(5,-8) AH26(6,-8) AH27(7,-8) AH28(8,-8) AH29(9,-8) AH30(10,-8) AH31(11,-8) AH32(12,-8) AH33(13,-8) AH34(14,-8) AH35(15,-8) AH36(16,-8) AH37(17,-8) AH38(18,-8) AH39(19,-8) AJ1(-19,-9) AJ2(-18,-9) AJ3(-17,-9) AJ4(-16,-9) AJ5(-15,-9) AJ6(-14,-9) AJ7(-13,-9) AJ8(-12,-9) AJ9(-11,-9) AJ10(-10,-9) AJ11(-9,-9) AJ12(-8,-9) AJ13(-7,-9) AJ14(-6,-9) AJ15(-5,-9) AJ16(-4,-9) AJ17(-3,-9) AJ18(-2,-9) AJ19(-1,-9) AJ20(0,-9) AJ21(1,-9) AJ22(2,-9) AJ23(3,-9) AJ24(4,-9) AJ25(5,-9) AJ26(6,-9) AJ27(7,-9) AJ28(8,-9) AJ29(9,-9) AJ30(10,-9) AJ31(11,-9) AJ32(12,-9) AJ33(13,-9) AJ34(14,-9) AJ35(15,-9) AJ36(16,-9) AJ37(17,-9) AJ38(18,-9) AJ39(19,-9) AK1(-19,-10) AK2(-18,-10) AK3(-17,-10) AK4(-16,-10) AK5(-15,-10) AK6(-14,-10) AK7(-13,-10) AK8(-12,-10) AK9(-11,-10) AK10(-10,-10) AK11(-9,-10) AK12(-8,-10) AK13(-7,-10) AK14(-6,-10) AK15(-5,-10) AK16(-4,-10) AK17(-3,-10) AK18(-2,-10) AK19(-1,-10) AK20(0,-10) AK21(1,-10) AK22(2,-10) AK23(3,-10) AK24(4,-10) AK25(5,-10) AK26(6,-10) AK27(7,-10) AK28(8,-10) AK29(9,-10) AK30(10,-10) AK31(11,-10) AK32(12,-10) AK33(13,-10) AK34(14,-10) AK35(15,-10) AK36(16,-10) AK37(17,-10) AK38(18,-10) AK39(19,-10) AL1(-19,-11) AL2(-18,-11) AL3(-17,-11) AL4(-16,-11) AL5(-15,-11) AL6(-14,-11) AL7(-13,-11) AL8(-12,-11) AL9(-11,-11) AL10(-10,-11) AL11(-9,-11) AL12(-8,-11) AL13(-7,-11) AL14(-6,-11) AL15(-5,-11) AL16(-4,-11) AL17(-3,-11) AL18(-2,-11) AL19(-1,-11) AL20(0,-11) AL21(1,-11) AL22(2,-11) AL23(3,-11) AL24(4,-11) AL25(5,-11) AL26(6,-11) AL27(7,-11) AL28(8,-11) AL29(9,-11) AL30(10,-11) AL31(11,-11) AL32(12,-11) AL33(13,-11) AL34(14,-11) AL35(15,-11) AL36(16,-11) AL37(17,-11) AL38(18,-11) AL39(19,-11) AM1(-19,-12) AM2(-18,-12) AM3(-17,-12) AM4(-16,-12) AM5(-15,-12) AM6(-14,-12) AM7(-13,-12) AM8(-12,-12) AM9(-11,-12) AM10(-10,-12) AM11(-9,-12) AM12(-8,-12) AM13(-7,-12) AM14(-6,-12) AM15(-5,-12) AM16(-4,-12) AM17(-3,-12) AM18(-2,-12) AM19(-1,-12) AM20(0,-12) AM21(1,-12) AM22(2,-12) AM23(3,-12) AM24(4,-12) AM25(5,-12) AM26(6,-12) AM27(7,-12) AM28(8,-12) AM29(9,-12) AM30(10,-12) AM31(11,-12) AM32(12,-12) AM33(13,-12) AM34(14,-12) AM35(15,-12) AM36(16,-12) AM37(17,-12) AM38(18,-12) AM39(19,-12) AN1(-19,-13) AN2(-18,-13) AN3(-17,-13) AN4(-16,-13) AN5(-15,-13) AN6(-14,-13) AN7(-13,-13) AN8(-12,-13) AN9(-11,-13) AN10(-10,-13) AN11(-9,-13) AN12(-8,-13) AN13(-7,-13) AN14(-6,-13) AN15(-5,-13) AN16(-4,-13) AN17(-3,-13) AN18(-2,-13) AN19(-1,-13) AN20(0,-13) AN21(1,-13) AN22(2,-13) AN23(3,-13) AN24(4,-13) AN25(5,-13) AN26(6,-13) AN27(7,-13) AN28(8,-13) AN29(9,-13) AN30(10,-13) AN31(11,-13) AN32(12,-13) AN33(13,-13) AN34(14,-13) AN35(15,-13) AN36(16,-13) AN37(17,-13) AN38(18,-13) AN39(19,-13) AP1(-19,-14) AP2(-18,-14) AP3(-17,-14) AP4(-16,-14) AP5(-15,-14) AP6(-14,-14) AP7(-13,-14) AP8(-12,-14) AP9(-11,-14) AP10(-10,-14) AP11(-9,-14) AP12(-8,-14) AP13(-7,-14) AP14(-6,-14) AP15(-5,-14) AP16(-4,-14) AP17(-3,-14) AP18(-2,-14) AP19(-1,-14) AP20(0,-14) AP21(1,-14) AP22(2,-14) AP23(3,-14) AP24(4,-14) AP25(5,-14) AP26(6,-14) AP27(7,-14) AP28(8,-14) AP29(9,-14) AP30(10,-14) AP31(11,-14) AP32(12,-14) AP33(13,-14) AP34(14,-14) AP35(15,-14) AP36(16,-14) AP37(17,-14) AP38(18,-14) AP39(19,-14) AR1(-19,-15) AR2(-18,-15) AR3(-17,-15) AR4(-16,-15) AR5(-15,-15) AR6(-14,-15) AR7(-13,-15) AR8(-12,-15) AR9(-11,-15) AR10(-10,-15) AR11(-9,-15) AR12(-8,-15) AR13(-7,-15) AR14(-6,-15) AR15(-5,-15) AR16(-4,-15) AR17(-3,-15) AR18(-2,-15) AR19(-1,-15) AR20(0,-15) AR21(1,-15) AR22(2,-15) AR23(3,-15) AR24(4,-15) AR25(5,-15) AR26(6,-15) AR27(7,-15) AR28(8,-15) AR29(9,-15) AR30(10,-15) AR31(11,-15) AR32(12,-15) AR33(13,-15) AR34(14,-15) AR35(15,-15) AR36(16,-15) AR37(17,-15) AR38(18,-15) AR39(19,-15) AT1(-19,-16) AT2(-18,-16) AT3(-17,-16) AT4(-16,-16) AT5(-15,-16) AT6(-14,-16) AT7(-13,-16) AT8(-12,-16) AT9(-11,-16) AT10(-10,-16) AT11(-9,-16) AT12(-8,-16) AT13(-7,-16) AT14(-6,-16) AT15(-5,-16) AT16(-4,-16) AT17(-3,-16) AT18(-2,-16) AT19(-1,-16) AT20(0,-16) AT21(1,-16) AT22(2,-16) AT23(3,-16) AT24(4,-16) AT25(5,-16) AT26(6,-16) AT27(7,-16) AT28(8,-16) AT29(9,-16) AT30(10,-16) AT31(11,-16) AT32(12,-16) AT33(13,-16) AT34(14,-16) AT35(15,-16) AT36(16,-16) AT37(17,-16) AT38(18,-16) AT39(19,-16) AU1(-19,-17) AU2(-18,-17) AU3(-17,-17) AU4(-16,-17) AU5(-15,-17) AU6(-14,-17) AU7(-13,-17) AU8(-12,-17) AU9(-11,-17) AU10(-10,-17) AU11(-9,-17) AU12(-8,-17) AU13(-7,-17) AU14(-6,-17) AU15(-5,-17) AU16(-4,-17) AU17(-3,-17) AU18(-2,-17) AU19(-1,-17) AU20(0,-17) AU21(1,-17) AU22(2,-17) AU23(3,-17) AU24(4,-17) AU25(5,-17) AU26(6,-17) AU27(7,-17) AU28(8,-17) AU29(9,-17) AU30(10,-17) AU31(11,-17) AU32(12,-17) AU33(13,-17) AU34(14,-17) AU35(15,-17) AU36(16,-17) AU37(17,-17) AU38(18,-17) AU39(19,-17) AV1(-19,-18) AV2(-18,-18) AV3(-17,-18) AV4(-16,-18) AV5(-15,-18) AV6(-14,-18) AV7(-13,-18) AV8(-12,-18) AV9(-11,-18) AV10(-10,-18) AV11(-9,-18) AV12(-8,-18) AV13(-7,-18) AV14(-6,-18) AV15(-5,-18) AV16(-4,-18) AV17(-3,-18) AV18(-2,-18) AV19(-1,-18) AV20(0,-18) AV21(1,-18) AV22(2,-18) AV23(3,-18) AV24(4,-18) AV25(5,-18) AV26(6,-18) AV27(7,-18) AV28(8,-18) AV29(9,-18) AV30(10,-18) AV31(11,-18) AV32(12,-18) AV33(13,-18) AV34(14,-18) AV35(15,-18) AV36(16,-18) AV37(17,-18) AV38(18,-18) AV39(19,-18) AW2(-18,-19) AW3(-17,-19) AW4(-16,-19) AW5(-15,-19) AW6(-14,-19) AW7(-13,-19) AW8(-12,-19) AW9(-11,-19) AW10(-10,-19) AW11(-9,-19) AW12(-8,-19) AW13(-7,-19) AW14(-6,-19) AW15(-5,-19) AW16(-4,-19) AW17(-3,-19) AW18(-2,-19) AW19(-1,-19) AW20(0,-19) AW21(1,-19) AW22(2,-19) AW23(3,-19) AW24(4,-19) AW25(5,-19) AW26(6,-19) AW27(7,-19) AW28(8,-19) AW29(9,-19) AW30(10,-19) AW31(11,-19) AW32(12,-19) AW33(13,-19) AW34(14,-19) AW35(15,-19) AW36(16,-19) AW37(17,-19) AW38(18,-19) B1(-19,18) B2(-18,18) B3(-17,18) B4(-16,18) B5(-15,18) B6(-14,18) B7(-13,18) B8(-12,18) B9(-11,18) B10(-10,18) B11(-9,18) B12(-8,18) B13(-7,18) B14(-6,18) B15(-5,18) B16(-4,18) B17(-3,18) B18(-2,18) B19(-1,18) B20(0,18) B21(1,18) B22(2,18) B23(3,18) B24(4,18) B25(5,18) B26(6,18) B27(7,18) B28(8,18) B29(9,18) B30(10,18) B31(11,18) B32(12,18) B33(13,18) B34(14,18) B35(15,18) B36(16,18) B37(17,18) B38(18,18) B39(19,18) C1(-19,17) C2(-18,17) C3(-17,17) C4(-16,17) C5(-15,17) C6(-14,17) C7(-13,17) C8(-12,17) C9(-11,17) C10(-10,17) C11(-9,17) C12(-8,17) C13(-7,17) C14(-6,17) C15(-5,17) C16(-4,17) C17(-3,17) C18(-2,17) C19(-1,17) C20(0,17) C21(1,17) C22(2,17) C23(3,17) C24(4,17) C25(5,17) C26(6,17) C27(7,17) C28(8,17) C29(9,17) C30(10,17) C31(11,17) C32(12,17) C33(13,17) C34(14,17) C35(15,17) C36(16,17) C37(17,17) C38(18,17) C39(19,17) D1(-19,16) D2(-18,16) D3(-17,16) D4(-16,16) D5(-15,16) D6(-14,16) D7(-13,16) D8(-12,16) D9(-11,16) D10(-10,16) D11(-9,16) D12(-8,16) D13(-7,16) D14(-6,16) D15(-5,16) D16(-4,16) D17(-3,16) D18(-2,16) D19(-1,16) D20(0,16) D21(1,16) D22(2,16) D23(3,16) D24(4,16) D25(5,16) D26(6,16) D27(7,16) D28(8,16) D29(9,16) D30(10,16) D31(11,16) D32(12,16) D33(13,16) D34(14,16) D35(15,16) D36(16,16) D37(17,16) D38(18,16) D39(19,16) E1(-19,15) E2(-18,15) E3(-17,15) E4(-16,15) E5(-15,15) E6(-14,15) E7(-13,15) E8(-12,15) E9(-11,15) E10(-10,15) E11(-9,15) E12(-8,15) E13(-7,15) E14(-6,15) E15(-5,15) E16(-4,15) E17(-3,15) E18(-2,15) E19(-1,15) E20(0,15) E21(1,15) E22(2,15) E23(3,15) E24(4,15) E25(5,15) E26(6,15) E27(7,15) E28(8,15) E29(9,15) E30(10,15) E31(11,15) E32(12,15) E33(13,15) E34(14,15) E35(15,15) E36(16,15) E37(17,15) E38(18,15) E39(19,15) F1(-19,14) F2(-18,14) F3(-17,14) F4(-16,14) F5(-15,14) F6(-14,14) F7(-13,14) F8(-12,14) F9(-11,14) F10(-10,14) F11(-9,14) F12(-8,14) F13(-7,14) F14(-6,14) F15(-5,14) F16(-4,14) F17(-3,14) F18(-2,14) F19(-1,14) F20(0,14) F21(1,14) F22(2,14) F23(3,14) F24(4,14) F25(5,14) F26(6,14) F27(7,14) F28(8,14) F29(9,14) F30(10,14) F31(11,14) F32(12,14) F33(13,14) F34(14,14) F35(15,14) F36(16,14) F37(17,14) F38(18,14) F39(19,14) G1(-19,13) G2(-18,13) G3(-17,13) G4(-16,13) G5(-15,13) G6(-14,13) G7(-13,13) G8(-12,13) G9(-11,13) G10(-10,13) G11(-9,13) G12(-8,13) G13(-7,13) G14(-6,13) G15(-5,13) G16(-4,13) G17(-3,13) G18(-2,13) G19(-1,13) G20(0,13) G21(1,13) G22(2,13) G23(3,13) G24(4,13) G25(5,13) G26(6,13) G27(7,13) G28(8,13) G29(9,13) G30(10,13) G31(11,13) G32(12,13) G33(13,13) G34(14,13) G35(15,13) G36(16,13) G37(17,13) G38(18,13) G39(19,13) H1(-19,12) H2(-18,12) H3(-17,12) H4(-16,12) H5(-15,12) H6(-14,12) H7(-13,12) H8(-12,12) H9(-11,12) H10(-10,12) H11(-9,12) H12(-8,12) H13(-7,12) H14(-6,12) H15(-5,12) H16(-4,12) H17(-3,12) H18(-2,12) H19(-1,12) H20(0,12) H21(1,12) H22(2,12) H23(3,12) H24(4,12) H25(5,12) H26(6,12) H27(7,12) H28(8,12) H29(9,12) H30(10,12) H31(11,12) H32(12,12) H33(13,12) H34(14,12) H35(15,12) H36(16,12) H37(17,12) H38(18,12) H39(19,12) J1(-19,11) J2(-18,11) J3(-17,11) J4(-16,11) J5(-15,11) J6(-14,11) J7(-13,11) J8(-12,11) J9(-11,11) J10(-10,11) J11(-9,11) J12(-8,11) J13(-7,11) J14(-6,11) J15(-5,11) J16(-4,11) J17(-3,11) J18(-2,11) J19(-1,11) J20(0,11) J21(1,11) J22(2,11) J23(3,11) J24(4,11) J25(5,11) J26(6,11) J27(7,11) J28(8,11) J29(9,11) J30(10,11) J31(11,11) J32(12,11) J33(13,11) J34(14,11) J35(15,11) J36(16,11) J37(17,11) J38(18,11) J39(19,11) K1(-19,10) K2(-18,10) K3(-17,10) K4(-16,10) K5(-15,10) K6(-14,10) K7(-13,10) K8(-12,10) K9(-11,10) K10(-10,10) K11(-9,10) K12(-8,10) K13(-7,10) K14(-6,10) K15(-5,10) K16(-4,10) K17(-3,10) K18(-2,10) K19(-1,10) K20(0,10) K21(1,10) K22(2,10) K23(3,10) K24(4,10) K25(5,10) K26(6,10) K27(7,10) K28(8,10) K29(9,10) K30(10,10) K31(11,10) K32(12,10) K33(13,10) K34(14,10) K35(15,10) K36(16,10) K37(17,10) K38(18,10) K39(19,10) L1(-19,9) L2(-18,9) L3(-17,9) L4(-16,9) L5(-15,9) L6(-14,9) L7(-13,9) L8(-12,9) L9(-11,9) L10(-10,9) L11(-9,9) L12(-8,9) L13(-7,9) L14(-6,9) L15(-5,9) L16(-4,9) L17(-3,9) L18(-2,9) L19(-1,9) L20(0,9) L21(1,9) L22(2,9) L23(3,9) L24(4,9) L25(5,9) L26(6,9) L27(7,9) L28(8,9) L29(9,9) L30(10,9) L31(11,9) L32(12,9) L33(13,9) L34(14,9) L35(15,9) L36(16,9) L37(17,9) L38(18,9) L39(19,9) M1(-19,8) M2(-18,8) M3(-17,8) M4(-16,8) M5(-15,8) M6(-14,8) M7(-13,8) M8(-12,8) M9(-11,8) M10(-10,8) M11(-9,8) M12(-8,8) M13(-7,8) M14(-6,8) M15(-5,8) M16(-4,8) M17(-3,8) M18(-2,8) M19(-1,8) M20(0,8) M21(1,8) M22(2,8) M23(3,8) M24(4,8) M25(5,8) M26(6,8) M27(7,8) M28(8,8) M29(9,8) M30(10,8) M31(11,8) M32(12,8) M33(13,8) M34(14,8) M35(15,8) M36(16,8) M37(17,8) M38(18,8) M39(19,8) N1(-19,7) N2(-18,7) N3(-17,7) N4(-16,7) N5(-15,7) N6(-14,7) N7(-13,7) N8(-12,7) N9(-11,7) N10(-10,7) N11(-9,7) N12(-8,7) N13(-7,7) N14(-6,7) N15(-5,7) N16(-4,7) N17(-3,7) N18(-2,7) N19(-1,7) N20(0,7) N21(1,7) N22(2,7) N23(3,7) N24(4,7) N25(5,7) N26(6,7) N27(7,7) N28(8,7) N29(9,7) N30(10,7) N31(11,7) N32(12,7) N33(13,7) N34(14,7) N35(15,7) N36(16,7) N37(17,7) N38(18,7) N39(19,7) P1(-19,6) P2(-18,6) P3(-17,6) P4(-16,6) P5(-15,6) P6(-14,6) P7(-13,6) P8(-12,6) P9(-11,6) P10(-10,6) P11(-9,6) P12(-8,6) P13(-7,6) P14(-6,6) P15(-5,6) P16(-4,6) P17(-3,6) P18(-2,6) P19(-1,6) P20(0,6) P21(1,6) P22(2,6) P23(3,6) P24(4,6) P25(5,6) P26(6,6) P27(7,6) P28(8,6) P29(9,6) P30(10,6) P31(11,6) P32(12,6) P33(13,6) P34(14,6) P35(15,6) P36(16,6) P37(17,6) P38(18,6) P39(19,6) R1(-19,5) R2(-18,5) R3(-17,5) R4(-16,5) R5(-15,5) R6(-14,5) R7(-13,5) R8(-12,5) R9(-11,5) R10(-10,5) R11(-9,5) R12(-8,5) R13(-7,5) R14(-6,5) R15(-5,5) R16(-4,5) R17(-3,5) R18(-2,5) R19(-1,5) R20(0,5) R21(1,5) R22(2,5) R23(3,5) R24(4,5) R25(5,5) R26(6,5) R27(7,5) R28(8,5) R29(9,5) R30(10,5) R31(11,5) R32(12,5) R33(13,5) R34(14,5) R35(15,5) R36(16,5) R37(17,5) R38(18,5) R39(19,5) T1(-19,4) T2(-18,4) T3(-17,4) T4(-16,4) T5(-15,4) T6(-14,4) T7(-13,4) T8(-12,4) T9(-11,4) T10(-10,4) T11(-9,4) T12(-8,4) T13(-7,4) T14(-6,4) T15(-5,4) T16(-4,4) T17(-3,4) T18(-2,4) T19(-1,4) T20(0,4) T21(1,4) T22(2,4) T23(3,4) T24(4,4) T25(5,4) T26(6,4) T27(7,4) T28(8,4) T29(9,4) T30(10,4) T31(11,4) T32(12,4) T33(13,4) T34(14,4) T35(15,4) T36(16,4) T37(17,4) T38(18,4) T39(19,4) U1(-19,3) U2(-18,3) U3(-17,3) U4(-16,3) U5(-15,3) U6(-14,3) U7(-13,3) U8(-12,3) U9(-11,3) U10(-10,3) U11(-9,3) U12(-8,3) U13(-7,3) U14(-6,3) U15(-5,3) U16(-4,3) U17(-3,3) U18(-2,3) U19(-1,3) U20(0,3) U21(1,3) U22(2,3) U23(3,3) U24(4,3) U25(5,3) U26(6,3) U27(7,3) U28(8,3) U29(9,3) U30(10,3) U31(11,3) U32(12,3) U33(13,3) U34(14,3) U35(15,3) U36(16,3) U37(17,3) U38(18,3) U39(19,3) V1(-19,2) V2(-18,2) V3(-17,2) V4(-16,2) V5(-15,2) V6(-14,2) V7(-13,2) V8(-12,2) V9(-11,2) V10(-10,2) V11(-9,2) V12(-8,2) V13(-7,2) V14(-6,2) V15(-5,2) V16(-4,2) V17(-3,2) V18(-2,2) V19(-1,2) V20(0,2) V21(1,2) V22(2,2) V23(3,2) V24(4,2) V25(5,2) V26(6,2) V27(7,2) V28(8,2) V29(9,2) V30(10,2) V31(11,2) V32(12,2) V33(13,2) V34(14,2) V35(15,2) V36(16,2) V37(17,2) V38(18,2) V39(19,2) W1(-19,1) W2(-18,1) W3(-17,1) W4(-16,1) W5(-15,1) W6(-14,1) W7(-13,1) W8(-12,1) W9(-11,1) W10(-10,1) W11(-9,1) W12(-8,1) W13(-7,1) W14(-6,1) W15(-5,1) W16(-4,1) W17(-3,1) W18(-2,1) W22(2,1) W23(3,1) W24(4,1) W25(5,1) W26(6,1) W27(7,1) W28(8,1) W29(9,1) W30(10,1) W31(11,1) W32(12,1) W33(13,1) W34(14,1) W35(15,1) W36(16,1) W37(17,1) W38(18,1) W39(19,1) Y1(-19,0) Y2(-18,0) Y3(-17,0) Y4(-16,0) Y5(-15,0) Y6(-14,0) Y7(-13,0) Y8(-12,0) Y9(-11,0) Y10(-10,0) Y11(-9,0) Y12(-8,0) Y13(-7,0) Y14(-6,0) Y15(-5,0) Y16(-4,0) Y17(-3,0) Y18(-2,0) Y22(2,0) Y23(3,0) Y24(4,0) Y25(5,0) Y26(6,0) Y27(7,0) Y28(8,0) Y29(9,0) Y30(10,0) Y31(11,0) Y32(12,0) Y33(13,0) Y34(14,0) Y35(15,0) Y36(16,0) Y37(17,0) Y38(18,0) Y39(19,0)
Top Overlay:
  circle w0.25: c-20.65,19 r0.125
  region: -19,20 -20,19 -20,20
  lines w0.2: -20,19 -19,20 ; -20,-20 20,-20 20,20 -20,20 -20,-20
Mechanical 13:
  lines w0.1: -20,-20 20,-20 20,20 -20,20 -20,-20
Mechanical 15:
  lines w0.1: -0.5,0 0.5,0 ; 0,-0.5 0,0.5 ; -21,-21 21,-21 21,21 -21,21 -21,-21
3D body: height 0, standoff 0, extent -20,-20 20,20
